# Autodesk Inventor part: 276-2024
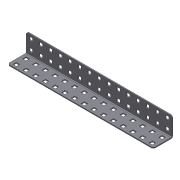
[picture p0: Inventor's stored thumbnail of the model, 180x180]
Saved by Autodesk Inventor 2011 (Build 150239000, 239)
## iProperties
Company: Autodesk Inc.
Created: 2005-08
Part Number: 276-2024
Document SubType Name: Sheet Metal
Designer: Autodesk Inc.
Density: 1 g/cm^3
Sheet Metal Rule: Default
Catalog Web Link: http://www.vexrobotics.com/chassis-kit.html
Description: 2x2x15 Bumper. This part has holes on 0.500" increments. This part is a versatile angle used in the small chassis kit.
Vendor: Innovation First, Inc.
Author: Autodesk Inc.
Title: VEX Robotics Kit of Parts
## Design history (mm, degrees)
node "Face1"
  sketch "Sketch1"
    geometry: L1 (-95.25, 24.13)-(95.25, 24.13); L2 (95.25, 24.13)-(95.25, 0); L3 (95.25, 0)-(-95.25, 0); L4 (-95.25, 0)-(-95.25, 24.13); L5 (-91.186, 21.336)-(-86.614, 21.336); L6 (-86.614, 21.336)-(-86.614, 16.764); L7 (-86.614, 16.764)-(-91.186, 16.764); L8 (-91.186, 16.764)-(-91.186, 21.336); L9 (-91.186, 8.636)-(-86.614, 8.636); L10 (-86.614, 8.636)-(-86.614, 4.064); L11 (-86.614, 4.064)-(-91.186, 4.064); L12 (-91.186, 4.064)-(-91.186, 8.636); L13 (-73.914, 21.336)-(-73.914, 16.764); L14 (-73.914, 16.764)-(-78.486, 16.764); L15 (-78.486, 16.764)-(-78.486, 21.336); L16 (-78.486, 21.336)-(-73.914, 21.336); L17 (-78.486, 4.064)-(-78.486, 8.636); L18 (-78.486, 8.636)-(-73.914, 8.636); L19 (-73.914, 4.064)-(-78.486, 4.064); L20 (-73.914, 8.636)-(-73.914, 4.064); L21 (-61.214, 21.336)-(-61.214, 16.764); L22 (-61.214, 16.764)-(-65.786, 16.764); L23 (-65.786, 16.764)-(-65.786, 21.336); L24 (-65.786, 21.336)-(-61.214, 21.336); L25 (-65.786, 4.064)-(-65.786, 8.636); L26 (-65.786, 8.636)-(-61.214, 8.636); L27 (-61.214, 4.064)-(-65.786, 4.064); L28 (-61.214, 8.636)-(-61.214, 4.064); L29 (-48.514, 21.336)-(-48.514, 16.764); L30 (-48.514, 16.764)-(-53.086, 16.764); L31 (-53.086, 16.764)-(-53.086, 21.336); L32 (-53.086, 21.336)-(-48.514, 21.336); L33 (-53.086, 4.064)-(-53.086, 8.636); L34 (-53.086, 8.636)-(-48.514, 8.636); L35 (-48.514, 4.064)-(-53.086, 4.064); L36 (-48.514, 8.636)-(-48.514, 4.064); L37 (-35.814, 21.336)-(-35.814, 16.764); L38 (-35.814, 16.764)-(-40.386, 16.764); L39 (-40.386, 16.764)-(-40.386, 21.336); L40 (-40.386, 21.336)-(-35.814, 21.336); L41 (-40.386, 4.064)-(-40.386, 8.636); L42 (-40.386, 8.636)-(-35.814, 8.636); L43 (-35.814, 4.064)-(-40.386, 4.064); L44 (-35.814, 8.636)-(-35.814, 4.064); L45 (-23.114, 21.336)-(-23.114, 16.764); L46 (-23.114, 16.764)-(-27.686, 16.764); L47 (-27.686, 16.764)-(-27.686, 21.336); L48 (-27.686, 21.336)-(-23.114, 21.336); L49 (-27.686, 4.064)-(-27.686, 8.636); L50 (-27.686, 8.636)-(-23.114, 8.636); L51 (-23.114, 4.064)-(-27.686, 4.064); L52 (-23.114, 8.636)-(-23.114, 4.064); L53 (-10.414, 21.336)-(-10.414, 16.764); L54 (-10.414, 16.764)-(-14.986, 16.764); L55 (-14.986, 16.764)-(-14.986, 21.336); L56 (-14.986, 21.336)-(-10.414, 21.336); L57 (-14.986, 4.064)-(-14.986, 8.636); L58 (-14.986, 8.636)-(-10.414, 8.636); L59 (-10.414, 4.064)-(-14.986, 4.064); L60 (-10.414, 8.636)-(-10.414, 4.064); L61 (2.286, 21.336)-(2.286, 16.764); L62 (2.286, 16.764)-(-2.286, 16.764); L63 (-2.286, 16.764)-(-2.286, 21.336); L64 (-2.286, 21.336)-(2.286, 21.336)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; 2 further points
    constraints: 248 end point, 6 parallel, 4 horizontal, 3 perpendicular, 2 collinear, 1 coincident, 1 midpoint, 224 other
    dimensions: "d0" = 2.794 distance between parallel lines of L1 L5; "d1" = 8.128 distance between parallel lines of L7 L9; "d2" = 4.572 distance of L7.end L5.start; "d3" = 4.572 distance of L11.end L9.start; "d4" = 4.572 distance of L5.start L5.end; "d5" = 24.13 distance of L3.end L1.start; "d8" = 12.7 distance of L5.end L13.start; "d13" = 4.064 distance between parallel lines of L2 L117; "d31" = 4.064 distance between parallel lines of L8 L4
node "Flange1"
feature "Corner Chamfer1" dims "d22" = 1.905, "d23" = 6.35, angle "d24" = 45 deg
sketch "Sketch3"
  geometry: L1 (0, 0)-(0, -21.361) reference; L2 (1.905, -23.266)-(188.595, -23.266) reference; L3 (4.064, -15.9)-(8.636, -15.9); L4 (8.636, -15.9)-(8.636, -20.472); L5 (8.636, -20.472)-(4.064, -20.472); L6 (4.064, -20.472)-(4.064, -15.9); L7 (4.064, -3.2)-(8.636, -3.2); L8 (8.636, -3.2)-(8.636, -7.772); L9 (8.636, -7.772)-(4.064, -7.772); L10 (4.064, -7.772)-(4.064, -3.2); L11 (16.764, -7.772)-(16.764, -3.2); L12 (16.764, -3.2)-(21.336, -3.2); L13 (21.336, -7.772)-(16.764, -7.772); L14 (21.336, -3.2)-(21.336, -7.772); L15 (21.336, -15.9)-(21.336, -20.472); L16 (16.764, -15.9)-(21.336, -15.9); L17 (21.336, -20.472)-(16.764, -20.472); L18 (16.764, -20.472)-(16.764, -15.9); L19 (29.464, -7.772)-(29.464, -3.2); L20 (29.464, -3.2)-(34.036, -3.2); L21 (34.036, -7.772)-(29.464, -7.772); L22 (34.036, -3.2)-(34.036, -7.772); L23 (34.036, -15.9)-(34.036, -20.472); L24 (29.464, -15.9)-(34.036, -15.9); L25 (34.036, -20.472)-(29.464, -20.472); L26 (29.464, -20.472)-(29.464, -15.9); L27 (42.164, -7.772)-(42.164, -3.2); L28 (42.164, -3.2)-(46.736, -3.2); L29 (46.736, -7.772)-(42.164, -7.772); L30 (46.736, -3.2)-(46.736, -7.772); L31 (46.736, -15.9)-(46.736, -20.472); L32 (42.164, -15.9)-(46.736, -15.9); L33 (46.736, -20.472)-(42.164, -20.472); L34 (42.164, -20.472)-(42.164, -15.9); L35 (54.864, -7.772)-(54.864, -3.2); L36 (54.864, -3.2)-(59.436, -3.2); L37 (59.436, -7.772)-(54.864, -7.772); L38 (59.436, -3.2)-(59.436, -7.772); L39 (59.436, -15.9)-(59.436, -20.472); L40 (54.864, -15.9)-(59.436, -15.9); L41 (59.436, -20.472)-(54.864, -20.472); L42 (54.864, -20.472)-(54.864, -15.9); L43 (67.564, -7.772)-(67.564, -3.2); L44 (67.564, -3.2)-(72.136, -3.2); L45 (72.136, -7.772)-(67.564, -7.772); L46 (72.136, -3.2)-(72.136, -7.772); L47 (72.136, -15.9)-(72.136, -20.472); L48 (67.564, -15.9)-(72.136, -15.9); L49 (72.136, -20.472)-(67.564, -20.472); L50 (67.564, -20.472)-(67.564, -15.9); L51 (80.264, -7.772)-(80.264, -3.2); L52 (80.264, -3.2)-(84.836, -3.2); L53 (84.836, -7.772)-(80.264, -7.772); L54 (84.836, -3.2)-(84.836, -7.772); L55 (84.836, -15.9)-(84.836, -20.472); L56 (80.264, -15.9)-(84.836, -15.9); L57 (84.836, -20.472)-(80.264, -20.472); L58 (80.264, -20.472)-(80.264, -15.9); L59 (92.964, -7.772)-(92.964, -3.2); L60 (92.964, -3.2)-(97.536, -3.2); L61 (97.536, -7.772)-(92.964, -7.772); L62 (97.536, -3.2)-(97.536, -7.772); L63 (97.536, -15.9)-(97.536, -20.472); L64 (92.964, -15.9)-(97.536, -15.9)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
  constraints: 240 end point, 4 parallel, 3 horizontal, 2 collinear, 2 perpendicular, 224 other
  dimensions: "d25" = 4.572 distance of L9.end L7.start; "d26" = 4.572 distance of L5.end L3.start; "d27" = 8.128 distance between parallel lines of L9 L3; "d28" = 4.064 distance between parallel lines of L1 L10; "d29" = 2.794 distance between parallel lines of L2 L5; "d30" = 4.572 distance of L4.end L5.end; "d34" = 12.7 distance of L9.end L11.start
cut "Cut1" sketch "Sketch3" dims "d39" = 1.27 (= Thickness), "d40" = 0
body "Solid1"
face "Plate1" dims "Thickness" = 1.27
sketch "Sketch2"
  geometry: L1 (190.5, 0)-(190.5, 24.13); L2 (190.5, 24.13)-(0, 24.13); 2 other entities
  constraints: 4 end point, 4 other
face "Plate2" dims "d15" = 1.27 (= BendReliefWidth), "d17" = 2.54 (= MinimumRemnant), "d19" = 24.13, "d20" = 90 deg, "d21" = 0.8636 (= BendRadius), "Thickness" = 1.27
bend "Bend1" dims "d15" = 1.27 (= BendReliefWidth), "d16" = 0.635 (= BendReliefDepth), "d17" = 2.54 (= MinimumRemnant), "d18" = 0.8636 (= BendRadius), "d19" = 24.13, "d20" = 90 deg, "d21" = 0.8636 (= BendRadius), "SeamGap" = 0.00508, "Thickness" = 1.27
other parameters: "BendRadius" = 0.8636, "BendReliefWidth" = 1.27 (= Thickness), "BendReliefDepth" = 0.635 (= 0.5 x Thickness), "CornerReliefSize" = 5.08 (= 4 x Thickness), "MinimumRemnant" = 2.54 (= 2 x Thickness), "TransitionRadius" = 0.8636 (= BendRadius), "d11" = 25.4, "d14" = 0.8636 (= BendRadius), "d37" = 25.4, "JacobiRadiusSize" = 1.27 (= Thickness), "GapSize" = 1.27 (= Thickness)
